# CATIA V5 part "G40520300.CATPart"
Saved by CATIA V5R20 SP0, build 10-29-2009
Part number: G40520300
Revision: 9
Definition: design
Nomenclature: G40520300
Source: made
Description: NOT SPECIFIED
Bounding box of the stored display mesh (mm): x -150 to 150, y -10 to 10, z -20 to 0
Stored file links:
  C:\Users\Raffaele\Desktop\3D X SITO CF\BOLEX\29-GUIDE STRIP REF 405\G40520300.CATPart
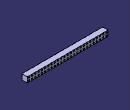
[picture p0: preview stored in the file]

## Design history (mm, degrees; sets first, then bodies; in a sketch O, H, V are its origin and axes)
Body1 "MANIFOLD_SOLID_BREP #7846" (main body)
  Solid1: solid without history
Body2 "MANIFOLD_SOLID_BREP #7984"
  Solid2: solid without history
Body3 "MANIFOLD_SOLID_BREP #8096"
  Solid3: solid without history
Body4 "MANIFOLD_SOLID_BREP #8208"
  Solid4: solid without history
Body5 "MANIFOLD_SOLID_BREP #8320"
  Solid5: solid without history
Body6 "MANIFOLD_SOLID_BREP #8432"
  Solid6: solid without history
Body7 "MANIFOLD_SOLID_BREP #8544"
  Solid7: solid without history
Body8 "MANIFOLD_SOLID_BREP #8656"
  Solid8: solid without history
Body9 "MANIFOLD_SOLID_BREP #8768"
  Solid9: solid without history
Body10 "MANIFOLD_SOLID_BREP #8880"
  Solid10: solid without history
Body11 "MANIFOLD_SOLID_BREP #8992"
  Solid11: solid without history
Body12 "MANIFOLD_SOLID_BREP #9104"
  Solid12: solid without history
Body13 "MANIFOLD_SOLID_BREP #9216"
  Solid13: solid without history
Body14 "MANIFOLD_SOLID_BREP #9328"
  Solid14: solid without history
Body15 "MANIFOLD_SOLID_BREP #9440"
  Solid15: solid without history
Body16 "MANIFOLD_SOLID_BREP #9552"
  Solid16: solid without history
Body17 "MANIFOLD_SOLID_BREP #9664"
  Solid17: solid without history
Body18 "MANIFOLD_SOLID_BREP #9776"
  Solid18: solid without history
Body19 "MANIFOLD_SOLID_BREP #9888"
  Solid19: solid without history
Body20 "MANIFOLD_SOLID_BREP #10000"
  Solid20: solid without history
Body21 "MANIFOLD_SOLID_BREP #10112"
  Solid21: solid without history
Body22 "MANIFOLD_SOLID_BREP #10224"
  Solid22: solid without history
Body23 "MANIFOLD_SOLID_BREP #10336"
  Solid23: solid without history
Body24 "MANIFOLD_SOLID_BREP #10448"
  Solid24: solid without history
Body25 "MANIFOLD_SOLID_BREP #10560"
  Solid25: solid without history
Body26 "MANIFOLD_SOLID_BREP #10672"
  Solid26: solid without history
Body27 "MANIFOLD_SOLID_BREP #10810"
  Solid27: solid without history
Body28 "MANIFOLD_SOLID_BREP #10948"
  Solid28: solid without history
Body29 "MANIFOLD_SOLID_BREP #11086"
  Solid29: solid without history
Body30 "MANIFOLD_SOLID_BREP #11224"
  Solid30: solid without history
Body31 "MANIFOLD_SOLID_BREP #11362"
  Solid31: solid without history
Body32 "MANIFOLD_SOLID_BREP #11500"
  Solid32: solid without history
Body33 "MANIFOLD_SOLID_BREP #11638"
  Solid33: solid without history
Body34 "MANIFOLD_SOLID_BREP #11776"
  Solid34: solid without history
Body35 "MANIFOLD_SOLID_BREP #11914"
  Solid35: solid without history
Body36 "MANIFOLD_SOLID_BREP #12052"
  Solid36: solid without history
Body37 "MANIFOLD_SOLID_BREP #12190"
  Solid37: solid without history
Body38 "MANIFOLD_SOLID_BREP #12328"
  Solid38: solid without history
Body39 "MANIFOLD_SOLID_BREP #12466"
  Solid39: solid without history
Body40 "MANIFOLD_SOLID_BREP #12604"
  Solid40: solid without history
Body41 "MANIFOLD_SOLID_BREP #12742"
  Solid41: solid without history
Body42 "MANIFOLD_SOLID_BREP #12880"
  Solid42: solid without history
Body43 "MANIFOLD_SOLID_BREP #13018"
  Solid43: solid without history
Body44 "MANIFOLD_SOLID_BREP #13156"
  Solid44: solid without history
Body45 "MANIFOLD_SOLID_BREP #13294"
  Solid45: solid without history
Body46 "MANIFOLD_SOLID_BREP #13432"
  Solid46: solid without history
Body47 "MANIFOLD_SOLID_BREP #13570"
  Solid47: solid without history
Body48 "MANIFOLD_SOLID_BREP #13708"
  Solid48: solid without history
Body49 "MANIFOLD_SOLID_BREP #13846"
  Solid49: solid without history
Body50 "MANIFOLD_SOLID_BREP #13958"
  Solid50: solid without history
Body51 "MANIFOLD_SOLID_BREP #14070"
  Solid51: solid without history
Body52 "MANIFOLD_SOLID_BREP #14182"
  Solid52: solid without history
Body53 "MANIFOLD_SOLID_BREP #14294"
  Solid53: solid without history
Body54 "MANIFOLD_SOLID_BREP #14406"
  Solid54: solid without history
Body55 "MANIFOLD_SOLID_BREP #14518"
  Solid55: solid without history
Body56 "MANIFOLD_SOLID_BREP #14630"
  Solid56: solid without history
Body57 "MANIFOLD_SOLID_BREP #14742"
  Solid57: solid without history
Body58 "MANIFOLD_SOLID_BREP #14854"
  Solid58: solid without history
Body59 "MANIFOLD_SOLID_BREP #14966"
  Solid59: solid without history
Body60 "MANIFOLD_SOLID_BREP #15078"
  Solid60: solid without history
Body61 "MANIFOLD_SOLID_BREP #15190"
  Solid61: solid without history
Body62 "MANIFOLD_SOLID_BREP #15302"
  Solid62: solid without history
Body63 "MANIFOLD_SOLID_BREP #15414"
  Solid63: solid without history
Body64 "MANIFOLD_SOLID_BREP #15526"
  Solid64: solid without history
Body65 "MANIFOLD_SOLID_BREP #15638"
  Solid65: solid without history
Body66 "MANIFOLD_SOLID_BREP #15750"
  Solid66: solid without history
Body67 "MANIFOLD_SOLID_BREP #15862"
  Solid67: solid without history
Body68 "MANIFOLD_SOLID_BREP #15974"
  Solid68: solid without history
Body69 "MANIFOLD_SOLID_BREP #16086"
  Solid69: solid without history
Body70 "MANIFOLD_SOLID_BREP #16198"
  Solid70: solid without history
Body71 "MANIFOLD_SOLID_BREP #16310"
  Solid71: solid without history
Body72 "MANIFOLD_SOLID_BREP #16422"
  Solid72: solid without history
Body73 "MANIFOLD_SOLID_BREP #16534"
  Solid73: solid without history
Body74 "MANIFOLD_SOLID_BREP #16646"
  Solid74: solid without history
Body75 "MANIFOLD_SOLID_BREP #16758"
  Solid75: solid without history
